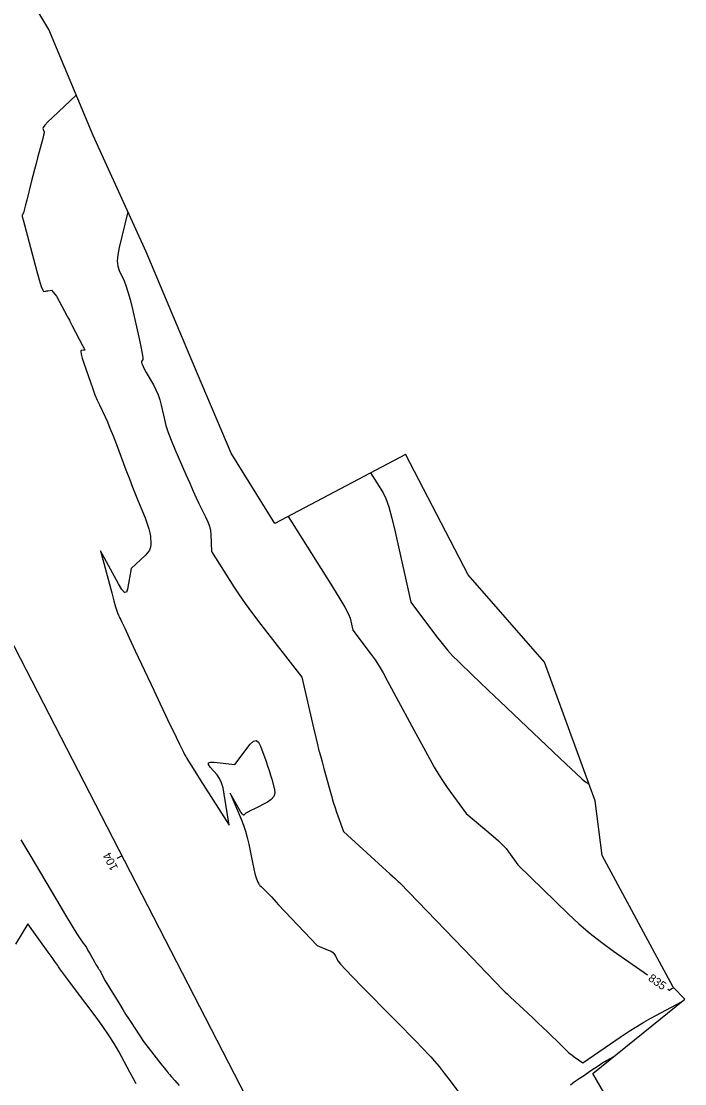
# Model space of a CAD drawing. Extents: x 1715724 to 1716561, y 394063 to 395906.
# Drawn here: x 1716169.2 to 1716281.4, y 394769.7 to 394949.5 of the extents above; entities that cross this region are included whole.
import ezdxf

# ---------------------------------------------------------------- set-up
doc = ezdxf.new("R2010")
doc.units = 0
for name, color, linetype in [('DT_X_Contour_Major', 7, 'Continuous'), ('DT_X_Contour_Minor', 7, 'Continuous'), ('DT_X_TIN_Hull', 7, 'Continuous'), ('GE_P_CL_10', 7, 'Continuous')]:
    doc.layers.add(name, color=color, linetype=linetype)

msp = doc.modelspace()

# ---------------------------------------------------------------- linework, layer by layer
at = {"layer": 'DT_X_Contour_Major'}
for points in [[(1716214.27, 394865.71), (1716221.49, 394854.28), (1716222.85, 394852.08), (1716223.86, 394850.39), (1716224.5, 394849.21), (1716224.77, 394848.52), (1716225.21, 394846.52), (1716228.31, 394842.4), (1716228.98, 394841.46), (1716229.66, 394840.41), (1716230.36, 394839.25), (1716231.06, 394837.98), (1716233.68, 394833.09), (1716234.43, 394831.69), (1716235.21, 394830.26), (1716238.19, 394824.76), (1716238.99, 394823.33), (1716239.76, 394822.03), (1716240.5, 394820.88), (1716241.2, 394819.87), (1716244.4, 394815.49), (1716248.94, 394811.61), (1716249.84, 394810.83), (1716250.57, 394810.13), (1716251.14, 394809.52), (1716251.56, 394809), (1716253.12, 394806.76), (1716261.62, 394798.51), (1716263.46, 394796.79), (1716265.36, 394795.15), (1716267.31, 394793.61), (1716269.31, 394792.15), (1716275.05, 394788.15)], [(1716278.49, 394785.74), (1716278.75, 394785.56), (1716279.07, 394785.78), (1716279.17, 394785.84), (1716279.45, 394785.99)]]:
    msp.add_lwpolyline(points, dxfattribs=at)
at = {"layer": 'DT_X_Contour_Minor'}
for points in [[(1716178.46, 394937.06), (1716174.42, 394933.25), (1716173.67, 394932.52), (1716173.15, 394931.97), (1716172.86, 394931.59), (1716172.8, 394931.39), (1716172.99, 394930.97), (1716173.02, 394930.9), (1716173.04, 394930.84), (1716173.05, 394930.81), (1716173.06, 394930.77), (1716173.03, 394930.64), (1716172.94, 394930.28), (1716172.79, 394929.69), (1716171.92, 394926.41), (1716171.67, 394925.45), (1716171.41, 394924.45), (1716171.14, 394923.4), (1716170.86, 394922.29), (1716170.1, 394919.27), (1716169.85, 394918.27), (1716169.65, 394917.55), (1716169.52, 394917.1), (1716169.45, 394916.93), (1716169.35, 394916.83), (1716169.32, 394916.78), (1716169.3, 394916.71), (1716169.31, 394916.62), (1716169.33, 394916.5), (1716169.47, 394915.93), (1716171.75, 394907.4), (1716172.19, 394905.81), (1716172.54, 394904.68), (1716172.79, 394904.01), (1716172.94, 394903.8), (1716173.31, 394903.88), (1716173.43, 394903.91), (1716173.55, 394903.93), (1716173.67, 394903.95), (1716174.28, 394904.03), (1716175.1, 394903), (1716176.93, 394899.65), (1716177.15, 394899.23), (1716177.31, 394898.94), (1716177.4, 394898.77), (1716177.8, 394898.01), (1716179.53, 394894.69), (1716179.74, 394894.28), (1716179.93, 394893.94), (1716179.95, 394893.91), (1716179.94, 394893.9), (1716179.89, 394893.89), (1716179.8, 394893.87), (1716179.68, 394893.86), (1716179.31, 394893.81), (1716179.24, 394893.66), (1716179.29, 394893.22), (1716179.49, 394892.5), (1716179.81, 394891.49), (1716180.86, 394888.44), (1716181.25, 394887.34), (1716181.63, 394886.34), (1716182.01, 394885.44), (1716182.37, 394884.63), (1716183.33, 394882.6), (1716183.72, 394881.74), (1716184.17, 394880.66), (1716184.68, 394879.38), (1716185.26, 394877.89), (1716186.87, 394873.62), (1716187.45, 394872.09), (1716187.99, 394870.7), (1716188.49, 394869.44), (1716188.94, 394868.31), (1716190.1, 394865.49), (1716190.48, 394864.51), (1716190.76, 394863.66), (1716190.93, 394862.95), (1716191, 394862.38), (1716191.05, 394861.04), (1716191, 394860.54), (1716190.83, 394860.05), (1716190.52, 394859.57), (1716190.09, 394859.11), (1716187.77, 394856.95), (1716187.15, 394853.42), (1716186.95, 394852.91), (1716186.63, 394852.89), (1716186.17, 394853.36), (1716185.59, 394854.32), (1716182.58, 394859.94), (1716184.47, 394852.8), (1716184.84, 394851.45), (1716185.12, 394850.44), (1716185.31, 394849.77), (1716185.42, 394849.45), (1716185.61, 394849.06), (1716185.67, 394848.91), (1716185.74, 394848.78), (1716185.8, 394848.66), (1716185.85, 394848.54), (1716185.99, 394848.25), (1716186.19, 394847.84), (1716186.66, 394846.83), (1716187.41, 394845.22), (1716188.44, 394843.01), (1716191.56, 394836.32), (1716192.64, 394834.02), (1716193.53, 394832.12), (1716194.24, 394830.64), (1716194.77, 394829.55), (1716195.92, 394827.22), (1716196.31, 394826.44), (1716196.6, 394825.86), (1716196.79, 394825.48), (1716196.89, 394825.31), (1716197.02, 394825.1), (1716197.07, 394825.02), (1716197.11, 394824.94), (1716197.15, 394824.87), (1716197.19, 394824.8), (1716197.28, 394824.62), (1716197.44, 394824.35), (1716197.86, 394823.69), (1716198.52, 394822.64), (1716199.44, 394821.19), (1716204.3, 394813.52), (1716203.49, 394818.74), (1716203.29, 394819.79), (1716203.02, 394820.67), (1716202.68, 394821.41), (1716202.28, 394821.99), (1716201.11, 394823.33), (1716200.83, 394823.76), (1716200.84, 394824.04), (1716201.15, 394824.17), (1716201.76, 394824.16), (1716205.3, 394823.77), (1716207.88, 394827.19), (1716208.41, 394827.72), (1716208.88, 394827.83), (1716209.29, 394827.54), (1716209.64, 394826.84), (1716210.5, 394824.42), (1716210.81, 394823.54), (1716211.08, 394822.72), (1716211.31, 394821.97), (1716211.51, 394821.28), (1716211.99, 394819.53), (1716212.04, 394818.9), (1716211.86, 394818.34), (1716211.44, 394817.84), (1716210.78, 394817.41), (1716208.7, 394816.34), (1716208.01, 394815.98), (1716207.49, 394815.71), (1716207.16, 394815.51), (1716207, 394815.39), (1716206.82, 394815.2), (1716206.72, 394815.21), (1716206.56, 394815.38), (1716206.32, 394815.71), (1716206.02, 394816.21), (1716204.47, 394818.91), (1716206.35, 394814.49), (1716206.73, 394813.51), (1716207.07, 394812.48), (1716207.37, 394811.4), (1716207.63, 394810.26), (1716208.26, 394807.16), (1716208.48, 394806.12), (1716208.67, 394805.31), (1716208.81, 394804.74), (1716208.92, 394804.41), (1716209.17, 394803.85), (1716209.26, 394803.66), (1716209.35, 394803.5), (1716209.43, 394803.38), (1716209.52, 394803.3), (1716209.73, 394803.13), (1716209.98, 394802.88), (1716210.55, 394802.29), (1716211.46, 394801.34), (1716212.69, 394800.03), (1716219.21, 394793.11), (1716221.04, 394792.34), (1716221.39, 394792.2), (1716221.64, 394792.09), (1716221.79, 394792.02), (1716221.85, 394791.99), (1716221.88, 394791.95), (1716221.92, 394791.9), (1716221.99, 394791.78), (1716222.11, 394791.58), (1716222.28, 394791.31), (1716222.77, 394790.5), (1716223.17, 394789.99), (1716223.99, 394789.09), (1716225.23, 394787.78), (1716226.89, 394786.08), (1716231.88, 394781.02), (1716233.59, 394779.28), (1716234.99, 394777.85), (1716236.06, 394776.75), (1716236.81, 394775.96), (1716238.4, 394774.28), (1716239.05, 394773.55), (1716239.81, 394772.63), (1716240.68, 394771.52), (1716241.67, 394770.22), (1716244.45, 394766.49)], [(1716187.2, 394917.3), (1716185.72, 394911.25), (1716185.48, 394910.03), (1716185.39, 394908.98), (1716185.47, 394908.09), (1716185.7, 394907.36), (1716186.54, 394905.64), (1716186.86, 394904.85), (1716187.21, 394903.78), (1716187.58, 394902.43), (1716187.98, 394900.8), (1716189.06, 394896.06), (1716189.4, 394894.5), (1716189.63, 394893.34), (1716189.74, 394892.6), (1716189.72, 394892.28), (1716189.52, 394891.96), (1716189.52, 394891.76), (1716189.64, 394891.39), (1716189.9, 394890.84), (1716190.29, 394890.13), (1716191.5, 394887.99), (1716191.92, 394887.18), (1716192.29, 394886.34), (1716192.58, 394885.47), (1716192.82, 394884.57), (1716193.37, 394882.14), (1716193.63, 394881.14), (1716194.02, 394879.97), (1716194.53, 394878.63), (1716195.16, 394877.12), (1716197, 394872.86), (1716197.66, 394871.35), (1716198.24, 394870.03), (1716198.76, 394868.9), (1716199.21, 394867.95), (1716200.33, 394865.66), (1716200.7, 394864.83), (1716200.97, 394864.07), (1716201.14, 394863.36), (1716201.22, 394862.71), (1716201.36, 394859.83), (1716205.1, 394853.85), (1716205.99, 394852.49), (1716207.04, 394850.98), (1716208.27, 394849.3), (1716209.68, 394847.47), (1716216.61, 394838.54), (1716218.58, 394829.94), (1716218.96, 394828.31), (1716219.23, 394827.13), (1716219.41, 394826.38), (1716219.49, 394826.07), (1716219.58, 394825.82), (1716219.65, 394825.58), (1716219.81, 394825.04), (1716220.04, 394824.2), (1716220.34, 394823.07), (1716221.27, 394819.65), (1716221.61, 394818.44), (1716221.93, 394817.37), (1716222.22, 394816.45), (1716222.48, 394815.68), (1716223.68, 394812.42), (1716230.26, 394806.38), (1716231.5, 394805.25), (1716232.38, 394804.44), (1716232.92, 394803.94), (1716233.1, 394803.78), (1716233.15, 394803.73), (1716245.45, 394790.96), (1716247.77, 394788.57), (1716249.42, 394786.84), (1716250.43, 394785.8), (1716250.78, 394785.44), (1716250.86, 394785.37), (1716250.99, 394785.24), (1716251.32, 394784.93), (1716251.86, 394784.43), (1716252.6, 394783.73), (1716254.86, 394781.62), (1716255.7, 394780.83), (1716256.54, 394780.03), (1716257.37, 394779.24), (1716258.19, 394778.44), (1716260.39, 394776.3), (1716261.15, 394775.57), (1716261.78, 394774.99), (1716262.29, 394774.56), (1716262.66, 394774.27), (1716264.1, 394773.27), (1716270.58, 394777.7), (1716271.94, 394778.61), (1716273.23, 394779.43), (1716274.45, 394780.16), (1716275.6, 394780.81), (1716280.83, 394783.61)], [(1716228.2, 394873.11), (1716230.35, 394869.71), (1716230.82, 394868.75), (1716231.32, 394867.34), (1716231.85, 394865.47), (1716232.4, 394863.14), (1716235.03, 394851.22), (1716239.38, 394845.43), (1716240.31, 394844.23), (1716241.24, 394843.12), (1716242.16, 394842.1), (1716243.08, 394841.17), (1716245.53, 394838.8), (1716246.65, 394837.73), (1716248.17, 394836.28), (1716250.08, 394834.46), (1716252.39, 394832.27), (1716259.09, 394825.92), (1716261.31, 394823.82), (1716262.94, 394822.3), (1716263.97, 394821.34), (1716264.42, 394820.96), (1716265.15, 394820.48)], [(1716169.1, 394810.99), (1716170.6, 394808.47), (1716175.12, 394800.84), (1716176.64, 394798.29), (1716177.79, 394796.38), (1716178.58, 394795.09), (1716179.01, 394794.44), (1716179.66, 394793.54), (1716179.91, 394793.18), (1716180.17, 394792.77), (1716180.45, 394792.31), (1716180.74, 394791.8), (1716181.53, 394790.39), (1716181.8, 394789.92), (1716182.01, 394789.56), (1716182.15, 394789.32), (1716182.23, 394789.19), (1716182.37, 394789.01), (1716182.43, 394788.92), (1716182.51, 394788.78), (1716182.62, 394788.59), (1716182.74, 394788.36), (1716183.38, 394787.17), (1716185.81, 394783.16), (1716186.32, 394782.32), (1716186.81, 394781.53), (1716187.28, 394780.78), (1716187.74, 394780.07), (1716189.82, 394776.87), (1716192.79, 394773.13), (1716193.35, 394772.43), (1716193.75, 394771.92), (1716194, 394771.6), (1716194.08, 394771.48), (1716194.1, 394771.41), (1716194.21, 394771.27), (1716194.55, 394770.89), (1716195.11, 394770.29), (1716195.89, 394769.46)], [(1716188.57, 394769.72), (1716188.12, 394770.54), (1716187.5, 394771.68), (1716185.64, 394775.17), (1716184.87, 394776.53), (1716183.94, 394778), (1716182.87, 394779.57), (1716181.64, 394781.24), (1716178.18, 394785.85), (1716177.04, 394787.37), (1716176.2, 394788.49), (1716175.68, 394789.2), (1716175.47, 394789.5), (1716175.33, 394789.76), (1716175.18, 394789.97), (1716174.87, 394790.42), (1716174.39, 394791.09), (1716173.73, 394792), (1716170.27, 394796.79), (1716168.18, 394793.38)], [(1716262.04, 394769.53), (1716262.68, 394770.03), (1716263.16, 394770.4), (1716263.48, 394770.62), (1716264.12, 394771.03), (1716264.38, 394771.21), (1716264.7, 394771.42), (1716265.07, 394771.67), (1716265.5, 394771.96), (1716266.7, 394772.78), (1716267.12, 394773.07), (1716267.5, 394773.31), (1716267.84, 394773.52), (1716268.13, 394773.68), (1716269.38, 394774.35)]]:
    msp.add_lwpolyline(points, dxfattribs=at)
at = {"layer": 'DT_X_TIN_Hull'}
msp.add_lwpolyline([(1716279.62, 394747.62), (1716265.79, 394771.45), (1716281.35, 394784.03), (1716279.37, 394786.08), (1716267.38, 394808.36), (1716266.2, 394817.63), (1716257.62, 394841.07), (1716244.72, 394855.86), (1716234.16, 394876.28), (1716234.11, 394876.25), (1716212.07, 394864.54), (1716204.66, 394876.44), (1716198.97, 394889.86), (1716190.28, 394910.55), (1716181.33, 394930.19), (1716173.81, 394948.17), (1716164.24, 394964.1)], dxfattribs=at)
at = {"layer": 'GE_P_CL_10'}
for p, q in [((1716249.46, 394685.42), (1715852.54, 395456.56)), ((1716186.22, 394808.29), (1716185.33, 394807.83))]:
    msp.add_line(p, q, dxfattribs=at)

# ---------------------------------------------------------------- texts
at = {"layer": 'DT_X_Contour_Major'}
msp.add_text('835', height=1.4, rotation=325.1025, dxfattribs=at).set_placement((1716275.05, 394787.29))
at = {"layer": 'GE_P_CL_10'}
msp.add_text('104', height=1.4, rotation=117.2357, dxfattribs=at).set_placement((1716185.58, 394806.25))

doc.saveas('drawing.dxf')
